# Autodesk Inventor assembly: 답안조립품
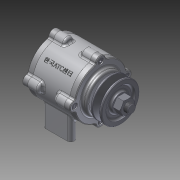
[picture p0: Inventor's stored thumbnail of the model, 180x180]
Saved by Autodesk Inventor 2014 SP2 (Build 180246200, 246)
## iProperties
Created: 2015-03
Part Number: 답안조립품
Document SubType Name: Assembly
Designer: 201-06
Author: 201-06
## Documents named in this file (11)
- C:\Users\201-06\Desktop\450305V1006\답안조립품.iam
- C:\Users\201-06\Desktop\450305V1006\본체.ipt
- C:\Users\201-06\Desktop\450305V1006\축.ipt
- C:\Users\201-06\Desktop\450305V1006\V벨트풀리.ipt
- C:\Users\201-06\Desktop\450305V1006\커버.ipt
- C:\Users\201-06\Desktop\450305V1006\커버2.ipt
- C:\Users\201-06\Desktop\450305V1006\베어링 6204.ipt
- C:\Users\201-06\Desktop\450305V1006\오일실.ipt
- C:\Users\201-06\Desktop\450305V1006\키(4 x 4 x 12).ipt
- C:\Users\201-06\Desktop\450305V1006\너트 M12x1.25.ipt
- C:\Users\201-06\Desktop\450305V1006\M 4 x 12.ipt
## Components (14 placed, 6 different names)
1. 그루브 풀리1:1 — 각도:1
2. KS B 2023 6204 - 20 x 47 x 14:1
3. KS B 2023 6204 - 20 x 47 x 14:2
4. KS B 2804 D D - 20 32 8:1
5. KS B 1311 (I) 4 x 4 x 12:1 — 각도:1
6. KS B 1012 클래스 1 일반 - 미터 M12x1.25:1
7. KS B 1003 - 미터 M 4 x 12:1
8. KS B 1003 - 미터 M 4 x 12:3
9. KS B 1003 - 미터 M 4 x 12:4
10. KS B 1003 - 미터 M 4 x 12:5
11. KS B 1003 - 미터 M 4 x 12:2
12. KS B 1003 - 미터 M 4 x 12:6
13. KS B 1003 - 미터 M 4 x 12:7
14. KS B 1003 - 미터 M 4 x 12:8
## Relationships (1: Angle 1)
- 각도:1 [Angle]: 그루브 풀리1:1 ↔ KS B 1311 (I) 4 x 4 x 12:1
